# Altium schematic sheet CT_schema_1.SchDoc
size 385 x 258 mm
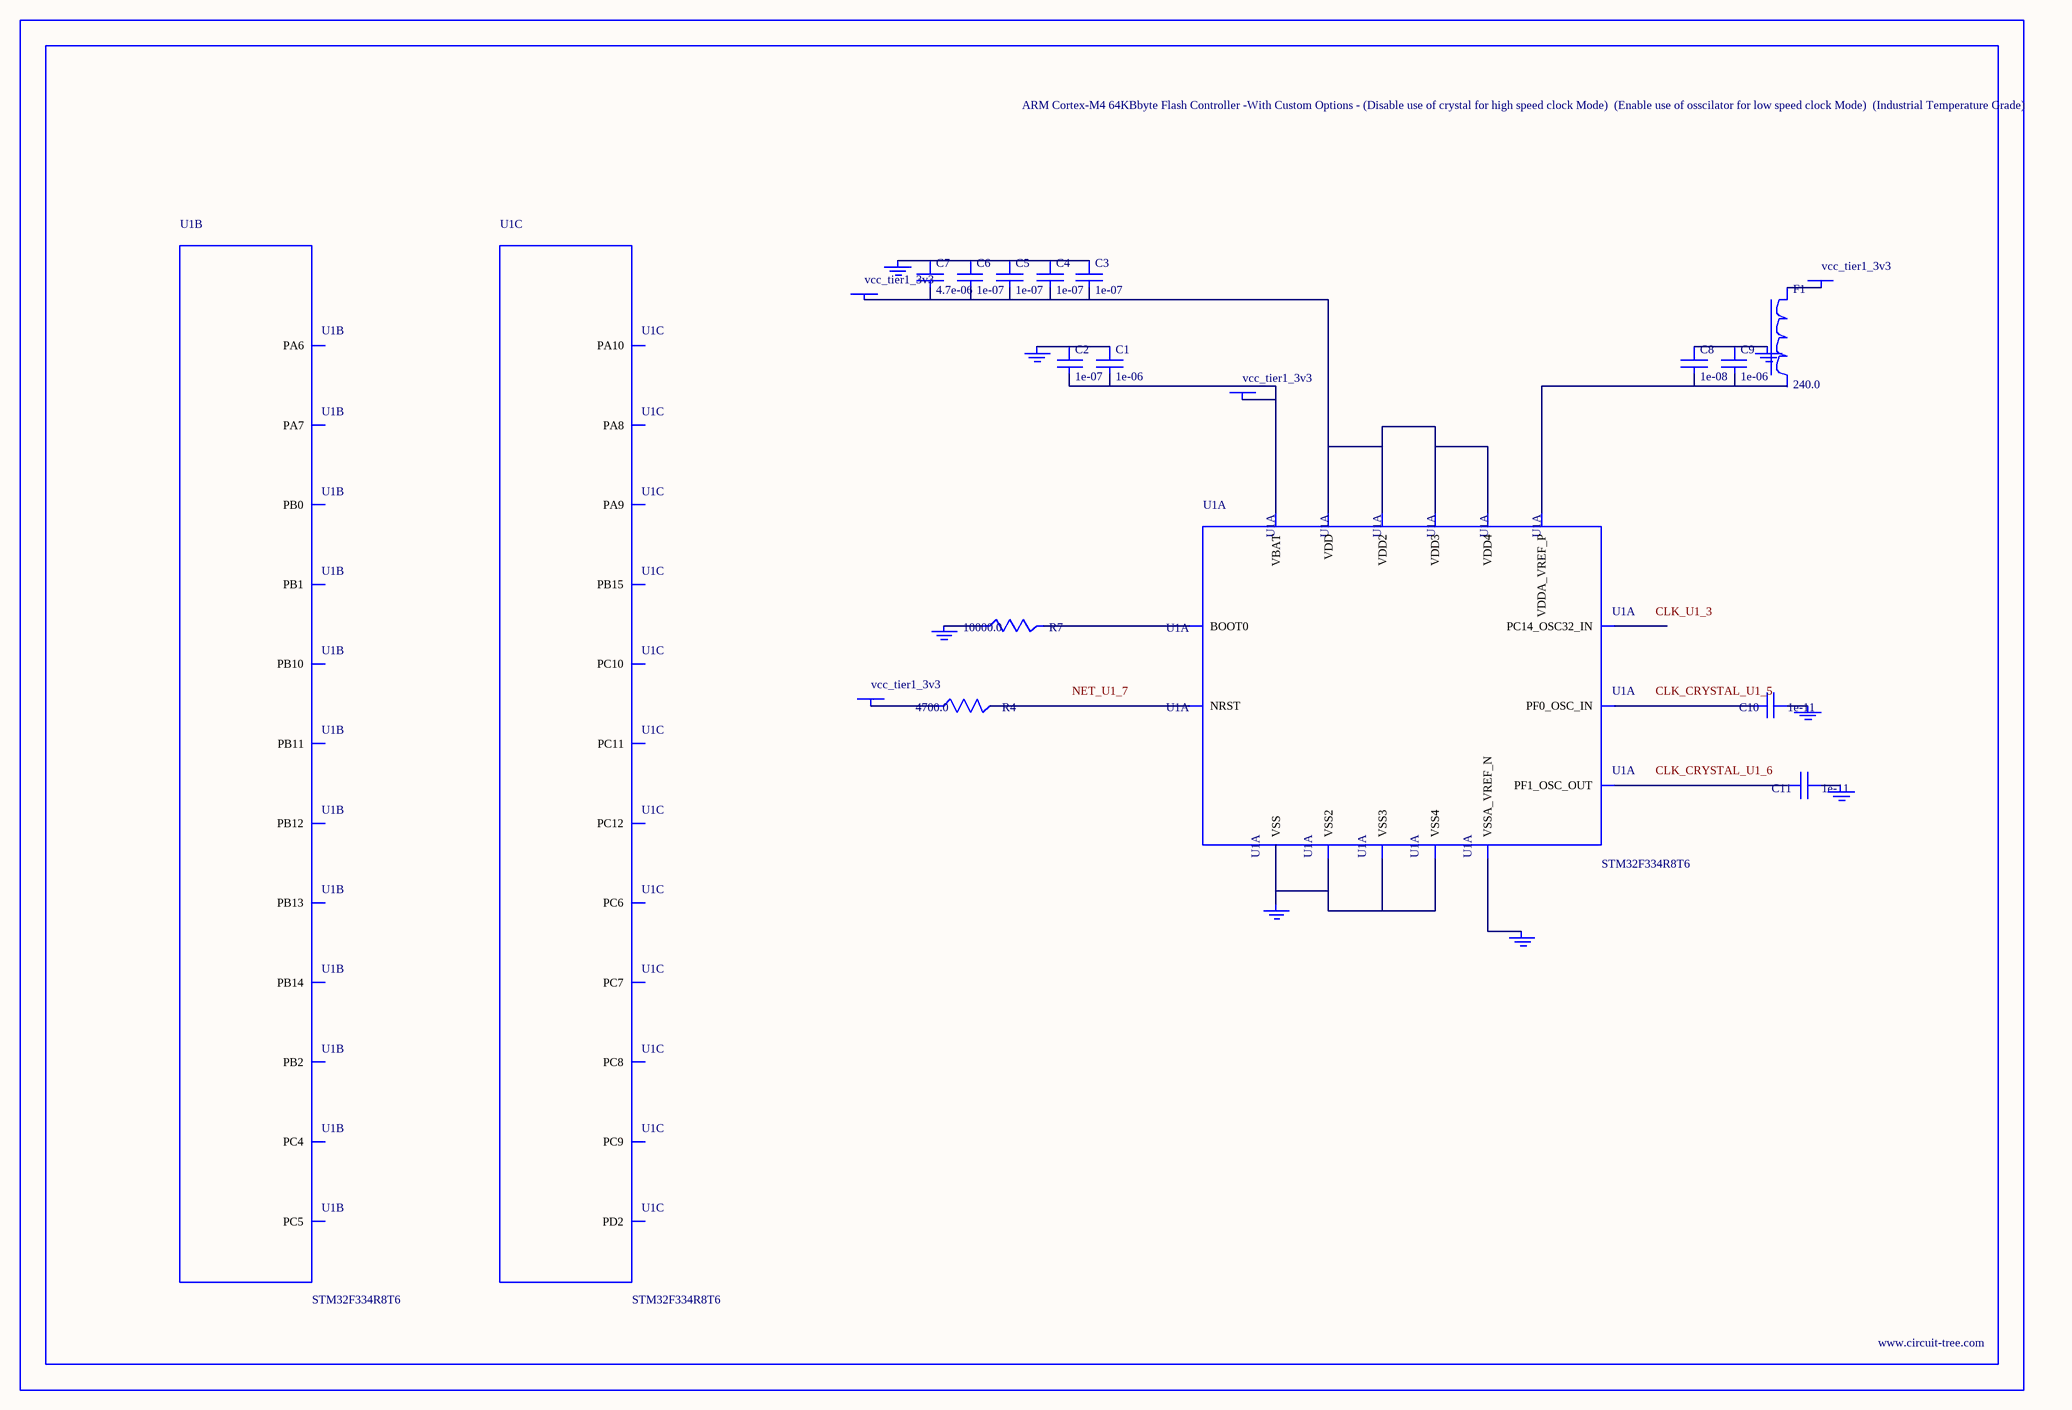
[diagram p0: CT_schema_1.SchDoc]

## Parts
BORDER0  (no value)
C1  1e-06  [C0603]
C2  1e-07  [C0603]
C3  1e-07  [C0603]
C4  1e-07  [C0603]
C5  1e-07  [C0603]
C6  1e-07  [C0603]
C7  4.7e-06  [C0603]
C8  1e-08  [C0603]
C9  1e-06  [C0603]
C10  1e-11  [C0402]
C11  1e-11  [C0402]
F1  240.0  [L0603]
GND_INSTANCE_0_0  (no value)
GND_INSTANCE_0_1  (no value)
GND_INSTANCE_0_2  (no value)
GND_INSTANCE_0_3  (no value)
GND_INSTANCE_0_4  (no value)
GND_INSTANCE_0_5  (no value)
GND_INSTANCE_0_6  (no value)
GND_INSTANCE_0_7  (no value)
POWER_INSTANCE_0_0  vcc_tier1_3v3
POWER_INSTANCE_0_1  vcc_tier1_3v3
POWER_INSTANCE_0_2  vcc_tier1_3v3
POWER_INSTANCE_0_3  vcc_tier1_3v3
R4  4700.0  [R0603]
R7  10000.0  [R0603]
U1  STM32F334R8T6  [LQFP64]  (parts A,B,C of 7)

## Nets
NetC1_1: C1.1 C2.1 GND_INSTANCE_0_0.0(GND)
NetC1_2: C1.2 C2.2 POWER_INSTANCE_0_0.0(PWR) U1.1(VBAT)
NetC3_1: C3.1 C4.1 C5.1 C6.1 C7.1 GND_INSTANCE_0_5.0(GND)
NetC3_2: C3.2 C4.2 C5.2 C6.2 C7.2 POWER_INSTANCE_0_2.0(PWR) U1.19(VDD) U1.32(VDD2) U1.48(VDD3) U1.64(VDD4)
NetC8_1: C8.1 C9.1 GND_INSTANCE_0_4.0(GND)
NetC8_2: C8.2 C9.2 U1.13(VDDA_VREF_P)
NetC10_1: C10.1 GND_INSTANCE_0_1.0(GND)
NetC10_2: C10.2 U1.5(PF0_OSC_IN)
NetC11_1: C11.1 GND_INSTANCE_0_2.0(GND)
NetC11_2: C11.2 U1.6(PF1_OSC_OUT)
NetF1_1: F1.1 POWER_INSTANCE_0_1.0(PWR)
NetGND_INSTANCE_0_3_0: GND_INSTANCE_0_3.0(GND) U1.12(VSSA_VREF_N)
NetGND_INSTANCE_0_6_0: GND_INSTANCE_0_6.0(GND) R7.1
NetGND_INSTANCE_0_7_0: GND_INSTANCE_0_7.0(GND) U1.18(VSS) U1.31(VSS2) U1.47(VSS3) U1.63(VSS4)
NetPOWER_INSTANCE_0_3_0: POWER_INSTANCE_0_3.0(PWR) R4.1
NetR4_2: R4.2 U1.7(NRST)
NetR7_2: R7.2 U1.60(BOOT0)

Not connected (* = marked no-connect by the designer): F1 2; U1 3(PC14_OSC32_IN) 22(PA6) 23(PA7) 24(PC4) 25(PC5) 26(PB0) 27(PB1) 28(PB2) 29(PB10) 30(PB11) 33(PB12) 34(PB13) 35(PB14) 36(PB15) 37(PC6) 38(PC7) 39(PC8) 40(PC9) 41(PA8) 42(PA9) 43(PA10) 51(PC10) 52(PC11) 53(PC12) 54(PD2)

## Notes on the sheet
- Labels drawn without touching a wire or pin: CLK_CRYSTAL_U1_5, CLK_CRYSTAL_U1_6, CLK_U1_3, NET_U1_7

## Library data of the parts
BORDER0 = BORDER_PAGE0
C1 C9 = C0603C105K3RACTU
C2-C6 = 06035C104K4Z2A
C7 = GRM188R6YA475KE15D
C8 = 06035C103K4Z2A
C10 C11 = C0402C100K3GACTU
F1 = Z0603C241ASMST
GND_INSTANCE_0_0-GND_INSTANCE_0_7 = GND
POWER_INSTANCE_0_0-POWER_INSTANCE_0_3 = PWR
R4 = RC0603JR-074K7L
R7 = RC0603JR-0710KL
